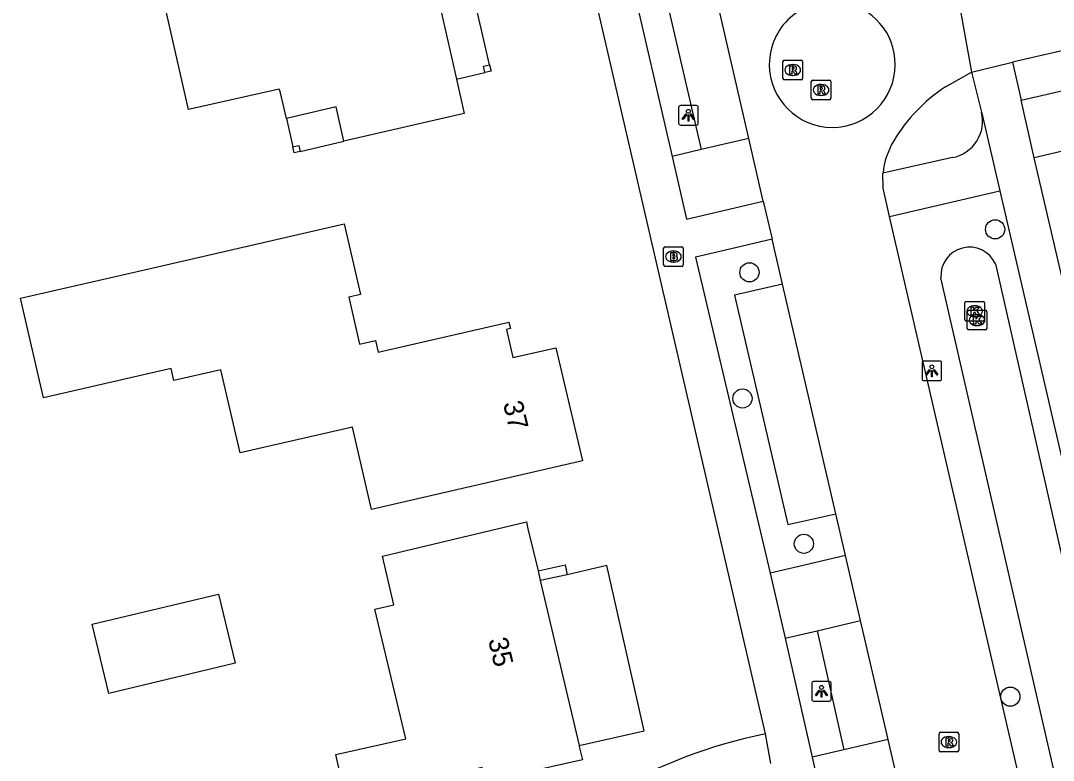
# Model space of a CAD drawing. Extents: x 156414 to 157775, y 382335 to 383765.
# Drawn here: x 156656.9 to 156709.6, y 382762.9 to 382800.7 of the extents above; entities that cross this region are included whole.
import ezdxf

# ---------------------------------------------------------------- set-up
doc = ezdxf.new("R2010")
doc.units = 0
for name, color, linetype in [('IMGEO_Berm_groen', 7, 'Continuous'), ('IMGEO_Boom', 7, 'Continuous'), ('IMGEO_Brandkraan', 7, 'Continuous'), ('IMGEO_Fietspad_open', 7, 'Continuous'), ('IMGEO_Greppel_droge_sloot', 7, 'Continuous'), ('IMGEO_Kolk', 7, 'Continuous'), ('IMGEO_Lichtpunt', 7, 'Continuous'), ('IMGEO_Muur', 7, 'Continuous'), ('IMGEO_Pand', 7, 'Continuous'), ('IMGEO_Pand_nummerreeks', 7, 'Continuous'), ('IMGEO_Pand_overbouw', 7, 'Continuous'), ('IMGEO_Parkeervlak_halfverhard', 7, 'Continuous'), ('IMGEO_Rijbaan_lokaal_gesloten', 7, 'Continuous'), ('IMGEO_Rijbaan_lokaal_open', 7, 'Continuous'), ('IMGEO_Rioolput', 7, 'Continuous'), ('IMGEO_Voetpad_open', 7, 'Continuous')]:
    doc.layers.add(name, color=color, linetype=linetype)

msp = doc.modelspace()

# ---------------------------------------------------------------- linework, layer by layer
at = {"layer": 'IMGEO_Berm_groen'}
msp.add_arc((156699.833, 382739.461), 25.304, 101.284, 120.6596, dxfattribs=at)
at = {"layer": 'IMGEO_Boom'}
for centre in [(156706.581, 382790.011), (156694.065, 382787.818), (156693.707, 382781.385), (156696.837, 382773.973), (156707.359, 382766.176)]:
    msp.add_circle(centre, 0.489, dxfattribs=at)
at = {"layer": 'IMGEO_Brandkraan'}
for p, q in [((156689.687, 382788.196), (156689.687, 382789.048)), ((156689.762, 382789.122), (156690.614, 382789.122)), ((156690.688, 382789.048), (156690.688, 382788.196)), ((156690.175, 382788.902), (156690.2, 382788.902)), ((156690.614, 382788.122), (156689.762, 382788.122)), ((156690.198, 382788.342), (156690.173, 382788.342))]:
    msp.add_line(p, q, dxfattribs=at)
for points in [[(156689.687, 382788.196), (156689.687, 382789.048)], [(156689.762, 382789.122), (156690.614, 382789.122)], [(156690.688, 382789.048), (156690.688, 382788.196)], [(156690.035, 382788.822), (156690.035, 382788.422), (156690.248, 382788.422)], [(156690.266, 382788.822), (156690.035, 382788.822)], [(156690.214, 382788.741), (156690.16, 382788.741), (156690.16, 382788.665)], [(156690.16, 382788.665), (156690.213, 382788.665)], [(156690.222, 382788.589), (156690.16, 382788.589), (156690.16, 382788.508)], [(156690.16, 382788.508), (156690.222, 382788.508)], [(156690.614, 382788.122), (156689.762, 382788.122)]]:
    msp.add_lwpolyline(points, dxfattribs=at)
for centre, radius, start, end in [((156689.764, 382789.046), 0.0765, 91.552, 178.448), ((156689.764, 382789.046), 0.0765, 91.552, 178.448), ((156690.612, 382789.046), 0.0765, 1.552, 88.448), ((156690.612, 382789.046), 0.0765, 1.552, 88.448), ((156690.215, 382788.703), 0.0379, 267.8285, 90.9355), ((156690.223, 382788.548), 0.0404, 269.8759, 90.5077), ((156690.27, 382788.677), 0.145, 59.4692, 91.5367), ((156690.295, 382788.724), 0.0922, 285.5137, 58.1501), ((156690.3, 382788.532), 0.105, 301.3115, 78.989), ((156689.764, 382788.198), 0.0765, 181.552, 268.448), ((156689.764, 382788.198), 0.0765, 181.552, 268.448), ((156690.254, 382788.673), 0.251, 268.6676, 293.5347), ((156690.612, 382788.198), 0.0765, 271.552, 358.448), ((156690.612, 382788.198), 0.0765, 271.552, 358.448)]:
    msp.add_arc(centre, radius, start, end, dxfattribs=at)
for centre, major_axis, ratio, start_param, end_param in [((156690.174, 382788.622), (-0.387, 0.002), 0.722429, 4.712389, 7.853982), ((156690.199, 382788.622), (-0.39, 0.002), 0.717154, 1.570796, 4.712389)]:
    msp.add_ellipse(centre, major_axis=major_axis, ratio=ratio, start_param=start_param, end_param=end_param, dxfattribs=at)
at = {"layer": 'IMGEO_Fietspad_open'}
for points in [[(156701.127, 382763.998), (156698.872, 382763.466)], [(156698.872, 382763.466), (156697.255, 382763.084)], [(156697.255, 382763.084), (156697.809, 382760.618)]]:
    msp.add_lwpolyline(points, dxfattribs=at)
at = {"layer": 'IMGEO_Greppel_droge_sloot'}
for points in [[(156706.6, 382788.257), (156715.273, 382750), (156715.513, 382748.943)], [(156712.807, 382748.354), (156712.43, 382750), (156703.82, 382787.544)]]:
    msp.add_lwpolyline(points, dxfattribs=at)
msp.add_arc((156705.276, 382787.644), 1.459, 24.8584, 183.9113, dxfattribs=at)
at = {"layer": 'IMGEO_Kolk'}
for p, q in [((156705.042, 382785.41), (156705.042, 382786.262)), ((156705.117, 382786.336), (156705.969, 382786.336)), ((156705.238, 382785.881), (156706.09, 382785.881)), ((156705.53, 382786.116), (156705.555, 382786.116)), ((156706.043, 382786.262), (156706.043, 382785.41)), ((156705.969, 382785.336), (156705.117, 382785.336)), ((156705.163, 382784.955), (156705.163, 382785.807)), ((156705.553, 382785.556), (156705.528, 382785.556)), ((156705.651, 382785.661), (156705.676, 382785.661)), ((156706.164, 382785.807), (156706.164, 382784.955)), ((156706.09, 382784.881), (156705.238, 382784.881)), ((156705.674, 382785.101), (156705.649, 382785.101))]:
    msp.add_line(p, q, dxfattribs=at)
for points in [[(156705.042, 382785.41), (156705.042, 382786.262)], [(156705.117, 382786.336), (156705.969, 382786.336)], [(156705.238, 382785.881), (156706.09, 382785.881)], [(156705.363, 382786.036), (156705.486, 382786.036), (156705.486, 382785.885), (156705.616, 382786.036), (156705.78, 382786.036), (156705.634, 382785.885), (156705.787, 382785.636), (156705.635, 382785.636), (156705.55, 382785.8), (156705.486, 382785.733), (156705.486, 382785.636), (156705.363, 382785.636), (156705.363, 382786.036)], [(156706.043, 382786.262), (156706.043, 382785.41)], [(156705.969, 382785.336), (156705.117, 382785.336)], [(156705.163, 382784.955), (156705.163, 382785.807)], [(156705.484, 382785.581), (156705.607, 382785.581), (156705.607, 382785.43), (156705.737, 382785.581), (156705.901, 382785.581), (156705.755, 382785.43), (156705.908, 382785.181), (156705.756, 382785.181), (156705.671, 382785.345), (156705.607, 382785.278), (156705.607, 382785.181), (156705.484, 382785.181), (156705.484, 382785.581)], [(156706.164, 382785.807), (156706.164, 382784.955)], [(156706.09, 382784.881), (156705.238, 382784.881)]]:
    msp.add_lwpolyline(points, dxfattribs=at)
for centre, start, end in [((156705.119, 382786.26), 91.552, 178.448), ((156705.119, 382786.26), 91.552, 178.448), ((156705.24, 382785.805), 91.552, 178.448), ((156705.24, 382785.805), 91.552, 178.448), ((156705.967, 382786.26), 1.552, 88.448), ((156705.967, 382786.26), 1.552, 88.448), ((156706.088, 382785.805), 1.552, 88.448), ((156706.088, 382785.805), 1.552, 88.448), ((156705.119, 382785.412), 181.552, 268.448), ((156705.119, 382785.412), 181.552, 268.448), ((156705.967, 382785.412), 271.552, 358.448), ((156705.967, 382785.412), 271.552, 358.448), ((156705.24, 382784.957), 181.552, 268.448), ((156705.24, 382784.957), 181.552, 268.448), ((156706.088, 382784.957), 271.552, 358.448), ((156706.088, 382784.957), 271.552, 358.448)]:
    msp.add_arc(centre, 0.0765, start, end, dxfattribs=at)
for centre, major_axis, ratio, start_param, end_param in [((156705.529, 382785.836), (-0.387, 0.002), 0.722429, 4.712389, 7.853982), ((156705.554, 382785.836), (-0.39, 0.002), 0.717154, 1.570796, 4.712389), ((156705.65, 382785.381), (-0.387, 0.002), 0.722429, 4.712389, 7.853982), ((156705.675, 382785.381), (-0.39, 0.002), 0.717154, 1.570796, 4.712389)]:
    msp.add_ellipse(centre, major_axis=major_axis, ratio=ratio, start_param=start_param, end_param=end_param, dxfattribs=at)
at = {"layer": 'IMGEO_Lichtpunt'}
for p, q in [((156690.456, 382796.233), (156690.456, 382795.426)), ((156690.456, 382796.233), (156690.456, 382795.426)), ((156691.358, 382796.328), (156690.55, 382796.328)), ((156691.358, 382796.328), (156690.55, 382796.328)), ((156691.452, 382795.426), (156691.452, 382796.233)), ((156691.452, 382795.426), (156691.452, 382796.233)), ((156690.55, 382795.332), (156691.358, 382795.332)), ((156690.55, 382795.332), (156691.358, 382795.332)), ((156703.762, 382783.295), (156702.954, 382783.295)), ((156703.762, 382783.295), (156702.954, 382783.295)), ((156702.86, 382783.2), (156702.86, 382782.393)), ((156702.86, 382783.2), (156702.86, 382782.393)), ((156703.856, 382782.393), (156703.856, 382783.2)), ((156703.856, 382782.393), (156703.856, 382783.2)), ((156702.954, 382782.299), (156703.762, 382782.299)), ((156702.954, 382782.299), (156703.762, 382782.299)), ((156698.138, 382766.944), (156697.33, 382766.944)), ((156698.138, 382766.944), (156697.33, 382766.944)), ((156697.236, 382766.849), (156697.236, 382766.042)), ((156697.236, 382766.849), (156697.236, 382766.042)), ((156698.232, 382766.042), (156698.232, 382766.849)), ((156698.232, 382766.042), (156698.232, 382766.849)), ((156697.33, 382765.948), (156698.138, 382765.948)), ((156697.33, 382765.948), (156698.138, 382765.948))]:
    msp.add_line(p, q, dxfattribs=at)
for points in [[(156690.83, 382795.897), (156690.869, 382795.869), (156690.681, 382795.607), (156690.643, 382795.634), (156690.83, 382795.897)], [(156690.932, 382795.849), (156690.979, 382795.849), (156690.979, 382795.527), (156690.932, 382795.527), (156690.932, 382795.849)], [(156691.042, 382795.869), (156691.08, 382795.896), (156691.267, 382795.634), (156691.228, 382795.606), (156691.042, 382795.869)], [(156703.234, 382782.864), (156703.273, 382782.836), (156703.085, 382782.574), (156703.047, 382782.601), (156703.234, 382782.864)], [(156703.336, 382782.816), (156703.383, 382782.816), (156703.383, 382782.494), (156703.336, 382782.494), (156703.336, 382782.816)], [(156703.446, 382782.836), (156703.484, 382782.863), (156703.671, 382782.601), (156703.632, 382782.573), (156703.446, 382782.836)], [(156697.61, 382766.513), (156697.649, 382766.485), (156697.461, 382766.223), (156697.423, 382766.25), (156697.61, 382766.513)], [(156697.712, 382766.465), (156697.759, 382766.465), (156697.759, 382766.143), (156697.712, 382766.143), (156697.712, 382766.465)], [(156697.822, 382766.485), (156697.86, 382766.512), (156698.047, 382766.25), (156698.008, 382766.222), (156697.822, 382766.485)]]:
    msp.add_lwpolyline(points, dxfattribs=at)
for centre in [(156690.955, 382796.031), (156703.359, 382782.998), (156697.735, 382766.647)]:
    msp.add_circle(centre, 0.0994, dxfattribs=at)
for centre, start, end in [((156690.55, 382796.233), 90, 180), ((156690.55, 382796.233), 90, 180), ((156691.358, 382796.233), 0, 90), ((156691.358, 382796.233), 0, 90), ((156690.55, 382795.426), 180, 270), ((156690.55, 382795.426), 180, 270), ((156691.358, 382795.426), 270, 0), ((156691.358, 382795.426), 270, 360), ((156702.954, 382783.2), 90, 180), ((156702.954, 382783.2), 90, 180), ((156703.762, 382783.2), 0, 90), ((156703.762, 382783.2), 0, 90), ((156702.954, 382782.393), 180, 270), ((156702.954, 382782.393), 180, 270), ((156703.762, 382782.393), 270, 0), ((156703.762, 382782.393), 270, 360), ((156697.33, 382766.849), 90, 180), ((156697.33, 382766.849), 90, 180), ((156698.138, 382766.849), 0, 90), ((156698.138, 382766.849), 0, 90), ((156697.33, 382766.042), 180, 270), ((156697.33, 382766.042), 180, 270), ((156698.138, 382766.042), 270, 0), ((156698.138, 382766.042), 270, 360)]:
    msp.add_arc(centre, 0.0946, start, end, dxfattribs=at)
at = {"layer": 'IMGEO_Muur'}
msp.add_lwpolyline([(156683.29, 382772.589), (156684.664, 382772.906), (156684.778, 382772.397), (156683.405, 382772.098)], dxfattribs=at)
at = {"layer": 'IMGEO_Pand'}
for points in [[(156675.778, 382808.226), (156676.601, 382804.483), (156679.273, 382805.109), (156680.034, 382801.82), (156678.286, 382801.416), (156679.128, 382797.673), (156679.524, 382795.913), (156673.388, 382794.503), (156673.009, 382796.255), (156670.471, 382795.673), (156670.155, 382797.037), (156670.089, 382797.168), (156665.481, 382796.126), (156663.974, 382802.73), (156665.447, 382803.066), (156665.416, 382803.203), (156668.926, 382804.004), (156669.22, 382802.718), (156670.506, 382803.011), (156669.636, 382806.823), (156675.778, 382808.226)], [(156680.821, 382798.411), (156680.897, 382798.078), (156680.584, 382798.006), (156680.507, 382798.339), (156680.821, 382798.411)], [(156671.163, 382793.99), (156670.856, 382793.918), (156670.786, 382794.224), (156671.099, 382794.294), (156671.163, 382793.99)], [(156718.228, 382792.821), (156718.043, 382792.78), (156717.172, 382792.587), (156715.143, 382792.137), (156714.679, 382794.165), (156712.105, 382793.576), (156711.909, 382794.434), (156708.578, 382793.666)], [(156711.612, 382780.598), (156708.578, 382793.666)], [(156663.457, 382788.005), (156673.404, 382790.298), (156674.235, 382786.693), (156673.641, 382786.556), (156674.193, 382784.158), (156675, 382784.341), (156675.136, 382783.739), (156681.807, 382785.279), (156681.881, 382784.951), (156681.676, 382784.905), (156681.998, 382783.468), (156684.201, 382783.976), (156685.564, 382778.209), (156674.807, 382775.722), (156673.837, 382779.918), (156668.108, 382778.608), (156667.121, 382782.845), (156664.732, 382782.299), (156664.592, 382782.912), (156658.084, 382781.424), (156656.923, 382786.499), (156663.457, 382788.005)], [(156683.405, 382772.098), (156685.382, 382763.692), (156685.394, 382763.64), (156685.55, 382762.951), (156680.611, 382761.841), (156680.449, 382762.563), (156678.322, 382762.085), (156678.867, 382759.634), (156674.363, 382757.07), (156672.986, 382763.218), (156676.548, 382764.016), (156674.976, 382770.634), (156675.949, 382770.866), (156675.36, 382773.347), (156682.696, 382775.089), (156682.778, 382774.743), (156683.29, 382772.589)], [(156683.29, 382772.589), (156683.405, 382772.098)], [(156667.006, 382771.399), (156667.853, 382767.888), (156661.419, 382766.33), (156660.564, 382769.877), (156667.006, 382771.399)]]:
    msp.add_lwpolyline(points, dxfattribs=at)
at = {"layer": 'IMGEO_Pand_overbouw'}
for points in [[(156680.821, 382798.411), (156680.034, 382801.82), (156678.286, 382801.416), (156679.128, 382797.673), (156680.584, 382798.006), (156680.507, 382798.339)], [(156671.163, 382793.99), (156673.388, 382794.503), (156673.009, 382796.255), (156670.471, 382795.673), (156670.786, 382794.224), (156671.099, 382794.294)], [(156686.79, 382772.863), (156684.778, 382772.397), (156683.405, 382772.098), (156685.382, 382763.692), (156688.693, 382764.44)]]:
    msp.add_lwpolyline(points, close=True, dxfattribs=at)
at = {"layer": 'IMGEO_Parkeervlak_halfverhard'}
for points in [[(156689.485, 382803.272), (156691.599, 382794.08)], [(156695.744, 382787.222), (156693.309, 382786.654), (156696.018, 382774.957), (156698.458, 382775.501)], [(156697.512, 382769.539), (156698.872, 382763.466)]]:
    msp.add_lwpolyline(points, dxfattribs=at)
at = {"layer": 'IMGEO_Rijbaan_lokaal_gesloten'}
for points in [[(156926.664, 382849.268), (156923.197, 382848.454), (156856.378, 382832.904), (156817.084, 382823.811), (156780.281, 382815.295), (156707.464, 382798.538)], [(156694.033, 382794.649), (156691.921, 382803.833)], [(156704.67, 382802.003), (156705.372, 382798.026)], [(156705.372, 382798.026), (156707.336, 382798.509), (156707.464, 382798.538)], [(156704.047, 382797.274), (156705.372, 382798.026)], [(156694.767, 382791.455), (156694.033, 382794.649)], [(156701.203, 382790.673), (156700.871, 382792.113), (156700.869, 382792.878)], [(156694.767, 382791.455), (156695.215, 382789.506)], [(156711.667, 382745.32), (156710.587, 382750), (156701.203, 382790.673)], [(156695.744, 382787.222), (156695.215, 382789.506)], [(156698.458, 382775.501), (156695.744, 382787.222)], [(156698.95, 382773.376), (156698.458, 382775.501)], [(156699.724, 382770.058), (156698.95, 382773.376)], [(156701.127, 382763.998), (156699.724, 382770.058)], [(156701.724, 382761.418), (156701.127, 382763.998)]]:
    msp.add_lwpolyline(points, dxfattribs=at)
for centre, radius, start, end in [((156708.737, 382790.161), 8.52, 123.4002, 149.1988), ((156704.705, 382792.511), 3.853, 148.5085, 174.5381)]:
    msp.add_arc(centre, radius, start, end, dxfattribs=at)
at = {"layer": 'IMGEO_Rijbaan_lokaal_open'}
for points in [[(156694.033, 382794.649), (156691.599, 382794.08)], [(156691.599, 382794.08), (156690.119, 382793.734)], [(156690.119, 382793.734), (156690.864, 382790.532), (156694.767, 382791.455)], [(156698.95, 382773.376), (156696.517, 382772.802), (156695.122, 382772.473)], [(156695.122, 382772.473), (156695.881, 382769.156)], [(156697.512, 382769.539), (156699.724, 382770.058)], [(156695.881, 382769.156), (156697.512, 382769.539)]]:
    msp.add_lwpolyline(points, dxfattribs=at)
for centre, radius, start, end in [((156698.283, 382798.424), 3.207, 83.9335, 180.0159), ((156698.284, 382798.422), 3.209, 0.0133, 81.4446), ((156698.285, 382798.424), 3.209, 180.0089, 359.9911)]:
    msp.add_arc(centre, radius, start, end, dxfattribs=at)
at = {"layer": 'IMGEO_Rioolput'}
for p, q in [((156695.771, 382797.714), (156695.771, 382798.566)), ((156695.846, 382798.64), (156696.698, 382798.64)), ((156696.772, 382798.566), (156696.772, 382797.714)), ((156696.259, 382798.42), (156696.284, 382798.42)), ((156696.698, 382797.64), (156695.846, 382797.64)), ((156696.282, 382797.86), (156696.257, 382797.86)), ((156697.213, 382796.696), (156697.213, 382797.548)), ((156697.288, 382797.622), (156698.14, 382797.622)), ((156698.214, 382797.548), (156698.214, 382796.696)), ((156697.701, 382797.402), (156697.726, 382797.402)), ((156698.14, 382796.622), (156697.288, 382796.622)), ((156697.724, 382796.842), (156697.699, 382796.842)), ((156703.727, 382763.433), (156703.727, 382764.285)), ((156703.802, 382764.359), (156704.654, 382764.359)), ((156704.728, 382764.285), (156704.728, 382763.433)), ((156704.215, 382764.139), (156704.24, 382764.139)), ((156704.654, 382763.359), (156703.802, 382763.359)), ((156704.238, 382763.579), (156704.213, 382763.579))]:
    msp.add_line(p, q, dxfattribs=at)
for points in [[(156695.771, 382797.714), (156695.771, 382798.566)], [(156695.846, 382798.64), (156696.698, 382798.64)], [(156696.772, 382798.566), (156696.772, 382797.714)], [(156696.36, 382798.338), (156696.108, 382798.34), (156696.108, 382797.94)], [(156696.108, 382797.94), (156696.232, 382797.94), (156696.232, 382798.102), (156696.243, 382798.102)], [(156696.286, 382798.259), (156696.232, 382798.259), (156696.232, 382798.178)], [(156696.232, 382798.178), (156696.284, 382798.178)], [(156696.29, 382798.073), (156696.361, 382797.94), (156696.501, 382797.94), (156696.436, 382798.066)], [(156696.698, 382797.64), (156695.846, 382797.64)], [(156697.213, 382796.696), (156697.213, 382797.548)], [(156697.288, 382797.622), (156698.14, 382797.622)], [(156698.214, 382797.548), (156698.214, 382796.696)], [(156697.802, 382797.32), (156697.55, 382797.322), (156697.55, 382796.922)], [(156697.55, 382796.922), (156697.674, 382796.922), (156697.674, 382797.084), (156697.685, 382797.084)], [(156697.728, 382797.241), (156697.674, 382797.241), (156697.674, 382797.16)], [(156697.674, 382797.16), (156697.726, 382797.16)], [(156697.732, 382797.055), (156697.803, 382796.922), (156697.943, 382796.922), (156697.878, 382797.048)], [(156698.14, 382796.622), (156697.288, 382796.622)], [(156703.727, 382763.433), (156703.727, 382764.285)], [(156703.802, 382764.359), (156704.654, 382764.359)], [(156704.728, 382764.285), (156704.728, 382763.433)], [(156704.316, 382764.057), (156704.064, 382764.059), (156704.064, 382763.659)], [(156704.064, 382763.659), (156704.188, 382763.659), (156704.188, 382763.821), (156704.199, 382763.821)], [(156704.242, 382763.978), (156704.188, 382763.978), (156704.188, 382763.897)], [(156704.188, 382763.897), (156704.24, 382763.897)], [(156704.246, 382763.792), (156704.317, 382763.659), (156704.457, 382763.659), (156704.392, 382763.785)], [(156704.654, 382763.359), (156703.802, 382763.359)]]:
    msp.add_lwpolyline(points, dxfattribs=at)
for centre, radius, start, end in [((156695.848, 382798.564), 0.0765, 91.552, 178.448), ((156695.848, 382798.564), 0.0765, 91.552, 178.448), ((156696.696, 382798.564), 0.0765, 1.552, 88.448), ((156696.696, 382798.564), 0.0765, 1.552, 88.448), ((156696.242, 382798.049), 0.0533, 26.0293, 88.6989), ((156696.268, 382798.367), 0.19, 274.7715, 282.9687), ((156696.292, 382798.163), 0.0964, 77.0061, 93.1865), ((156696.306, 382798.22), 0.0378, 276.6634, 79.6772), ((156696.359, 382798.228), 0.109, 350.3612, 89.416), ((156696.357, 382798.228), 0.112, 277.5842, 350.9817), ((156696.341, 382798.013), 0.108, 29.5134, 73.7905), ((156695.848, 382797.716), 0.0765, 181.552, 268.448), ((156695.848, 382797.716), 0.0765, 181.552, 268.448), ((156696.696, 382797.716), 0.0765, 271.552, 358.448), ((156696.696, 382797.716), 0.0765, 271.552, 358.448), ((156697.29, 382797.546), 0.0765, 91.552, 178.448), ((156697.29, 382797.546), 0.0765, 91.552, 178.448), ((156698.138, 382797.546), 0.0765, 1.552, 88.448), ((156698.138, 382797.546), 0.0765, 1.552, 88.448), ((156697.684, 382797.031), 0.0533, 26.0293, 88.6989), ((156697.71, 382797.349), 0.19, 274.7715, 282.9687), ((156697.734, 382797.145), 0.0964, 77.0061, 93.1865), ((156697.748, 382797.202), 0.0378, 276.6634, 79.6772), ((156697.801, 382797.21), 0.109, 350.3612, 89.416), ((156697.799, 382797.21), 0.112, 277.5842, 350.9817), ((156697.783, 382796.995), 0.108, 29.5134, 73.7905), ((156697.29, 382796.698), 0.0765, 181.552, 268.448), ((156697.29, 382796.698), 0.0765, 181.552, 268.448), ((156698.138, 382796.698), 0.0765, 271.552, 358.448), ((156698.138, 382796.698), 0.0765, 271.552, 358.448), ((156703.804, 382764.283), 0.0765, 91.552, 178.448), ((156703.804, 382764.283), 0.0765, 91.552, 178.448), ((156704.652, 382764.283), 0.0765, 1.552, 88.448), ((156704.652, 382764.283), 0.0765, 1.552, 88.448), ((156704.198, 382763.768), 0.0533, 26.0293, 88.6989), ((156704.224, 382764.086), 0.19, 274.7715, 282.9687), ((156704.248, 382763.882), 0.0964, 77.0061, 93.1865), ((156704.262, 382763.939), 0.0378, 276.6634, 79.6772), ((156704.315, 382763.947), 0.109, 350.3612, 89.416), ((156704.313, 382763.947), 0.112, 277.5842, 350.9817), ((156704.297, 382763.732), 0.108, 29.5134, 73.7905), ((156703.804, 382763.435), 0.0765, 181.552, 268.448), ((156703.804, 382763.435), 0.0765, 181.552, 268.448), ((156704.652, 382763.435), 0.0765, 271.552, 358.448), ((156704.652, 382763.435), 0.0765, 271.552, 358.448)]:
    msp.add_arc(centre, radius, start, end, dxfattribs=at)
for centre, major_axis, ratio, start_param, end_param in [((156696.258, 382798.14), (-0.387, 0.002), 0.722429, 4.712389, 7.853982), ((156696.283, 382798.14), (-0.39, 0.002), 0.717154, 1.570796, 4.712389), ((156697.7, 382797.122), (-0.387, 0.002), 0.722429, 4.712389, 7.853982), ((156697.725, 382797.122), (-0.39, 0.002), 0.717154, 1.570796, 4.712389), ((156704.214, 382763.859), (-0.387, 0.002), 0.722429, 4.712389, 7.853982), ((156704.239, 382763.859), (-0.39, 0.002), 0.717154, 1.570796, 4.712389)]:
    msp.add_ellipse(centre, major_axis=major_axis, ratio=ratio, start_param=start_param, end_param=end_param, dxfattribs=at)
at = {"layer": 'IMGEO_Voetpad_open'}
for points in [[(156694.882, 382764.275), (156665.21, 382892.732)], [(156707.908, 382796.596), (156778.432, 382812.831)], [(156689.485, 382803.272), (156688.01, 382802.932), (156690.119, 382793.734)], [(156707.464, 382798.538), (156707.908, 382796.596)], [(156705.372, 382798.026), (156705.887, 382795.997)], [(156708.578, 382793.666), (156707.908, 382796.596)], [(156705.887, 382795.997), (156705.913, 382795.934), (156706.821, 382791.977)], [(156704.405, 382793.672), (156700.869, 382792.878)], [(156701.203, 382790.673), (156706.821, 382791.977)], [(156706.821, 382791.977), (156711.484, 382771.868)], [(156695.215, 382789.506), (156692.782, 382788.931), (156691.321, 382788.585), (156695.122, 382772.473)], [(156695.881, 382769.156), (156697.255, 382763.084)], [(156695.147, 382762.767), (156694.882, 382764.275)]]:
    msp.add_lwpolyline(points, dxfattribs=at)
msp.add_arc((156704.054, 382795.531), 1.891, 280.6952, 14.2763, dxfattribs=at)

# ---------------------------------------------------------------- texts
at = {"layer": 'IMGEO_Pand_nummerreeks'}
for s, rotation, p in [('37', 283.2981, (156681.501, 382781.142)), ('35', 283.2294, (156680.741, 382769.074))]:
    msp.add_text(s, height=1, rotation=rotation, dxfattribs=at).set_placement(p)

doc.saveas('drawing.dxf')
